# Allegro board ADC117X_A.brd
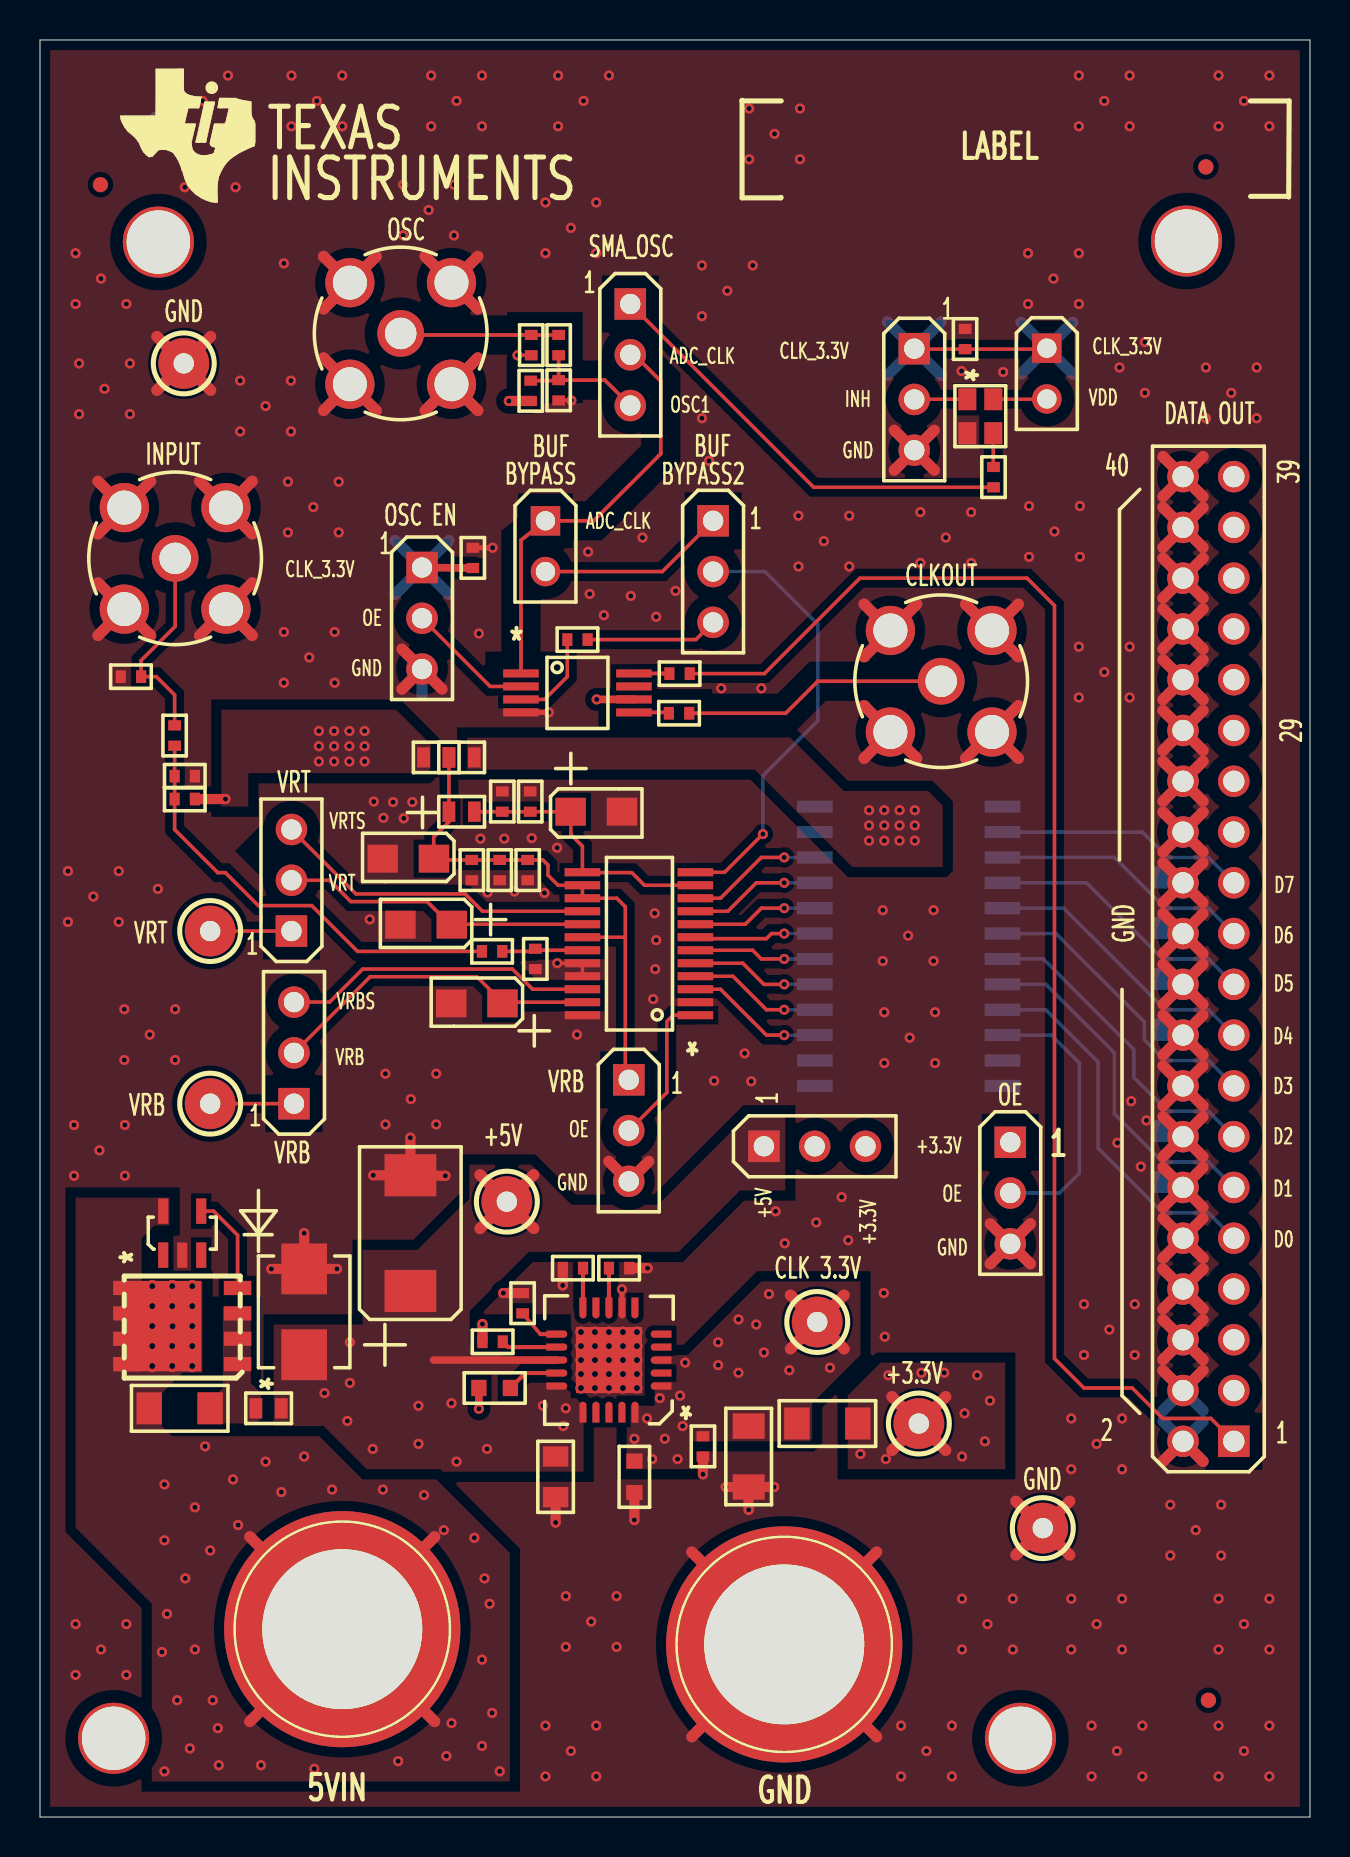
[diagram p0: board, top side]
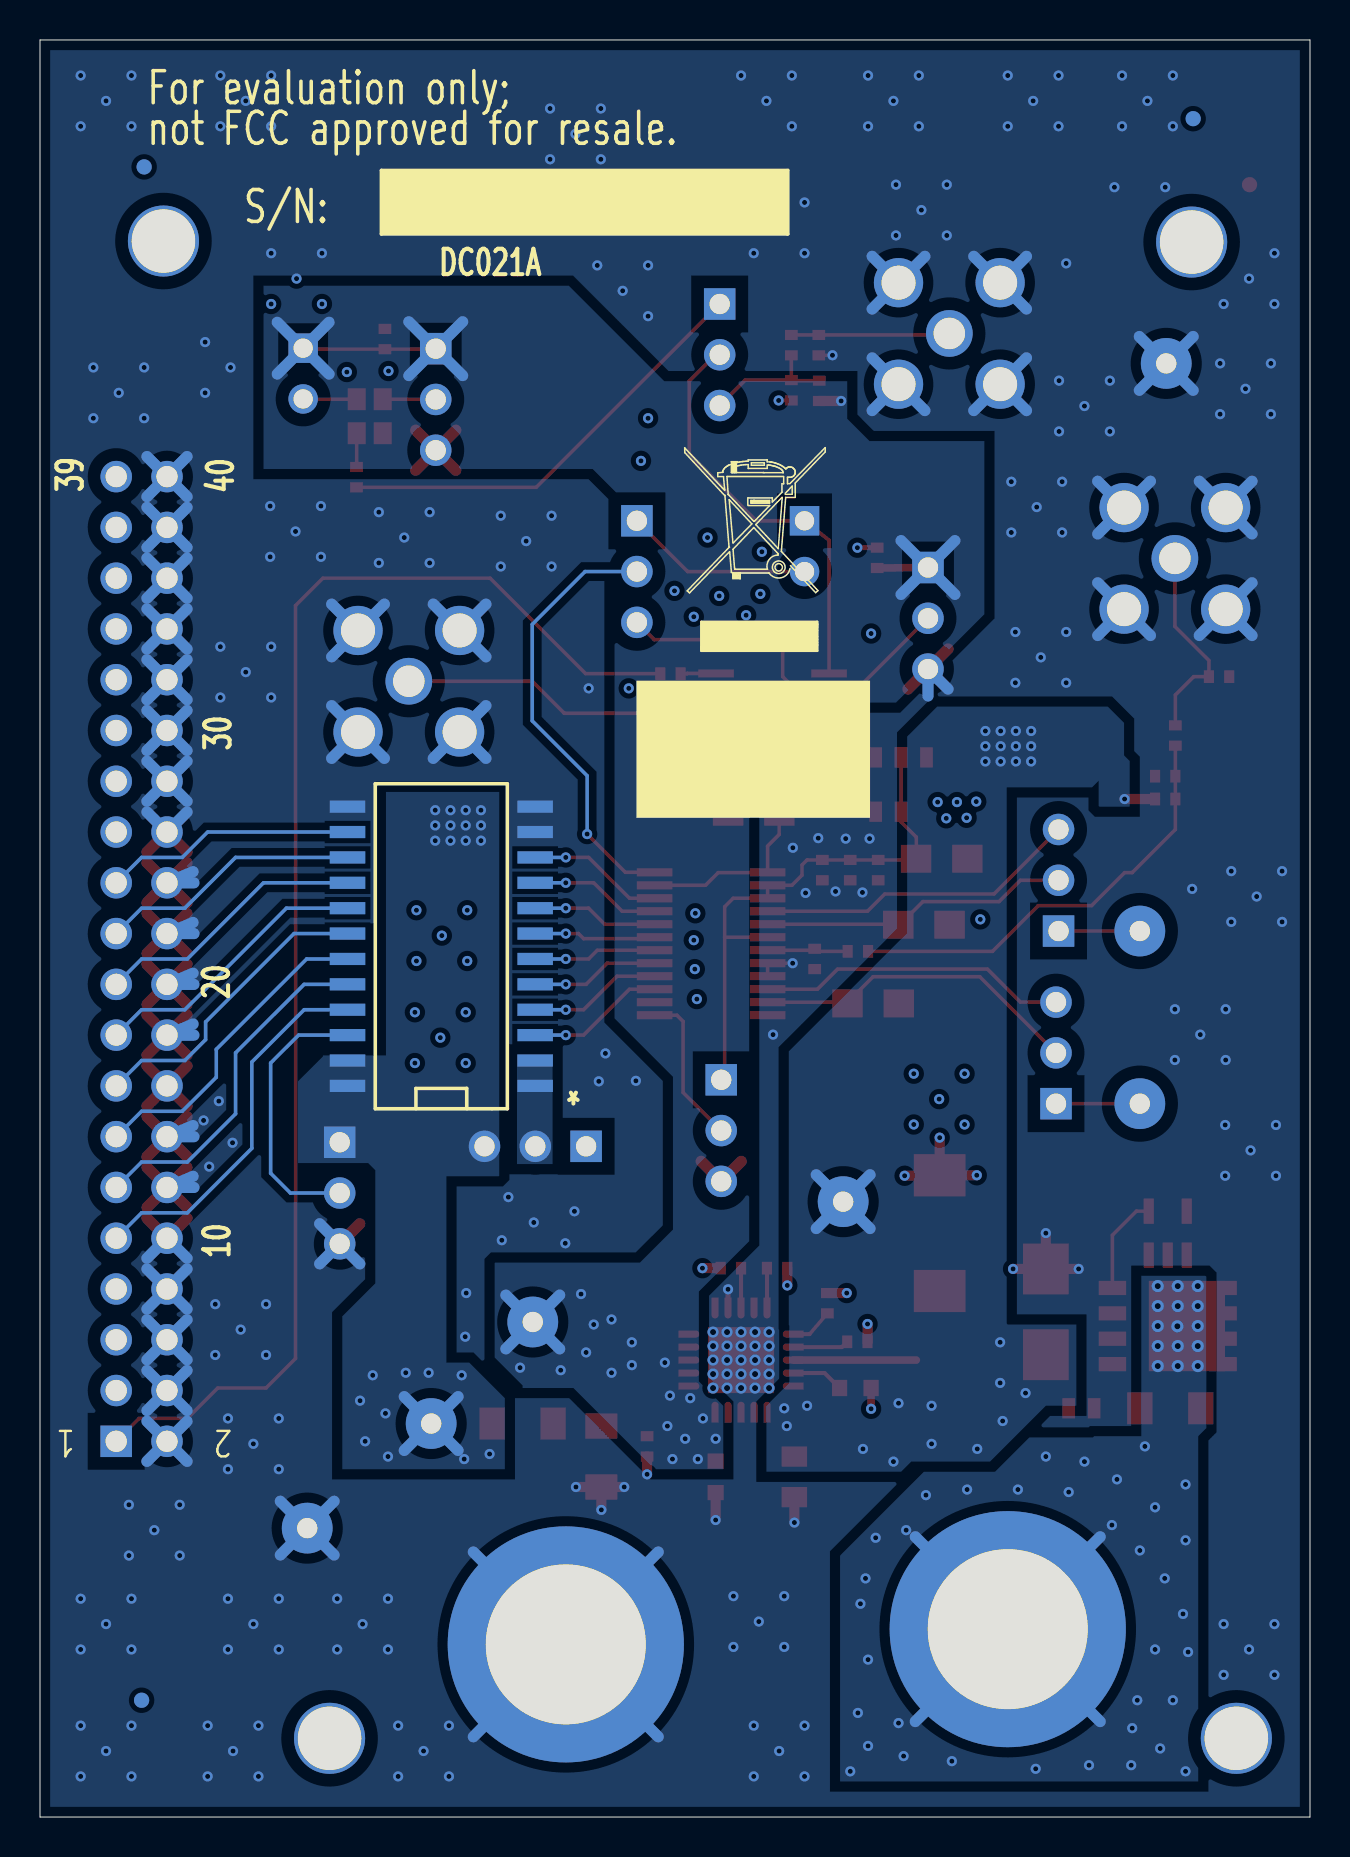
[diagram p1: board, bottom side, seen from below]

Outline 63.5 x 88.9 mm; copper layers: TOP, GND1, GND2, BOTTOM. Coordinates in mm from the lower left corner of the outline.
Outline path: 0,88.9 0,0 63.5,0 63.5,88.9 0,88.9

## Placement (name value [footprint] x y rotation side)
C1  10uF  [TANT_A]  18.41 47.94 180 top
C2  .1uF  [0402]  22.99 47.37 270 top
C3  .1uF  [0402]  21.59 47.37 270 top
C4  10uF  [TANT_A]  27.81 50.29 0 top
C5  .1uF  [0402]  24.51 50.8 90 top
C6  .1uF  [0402]  21.64 62.99 90 top
C7  10uF  [TANT_A]  19.3 44.64 180 top
C8  .01uF  [0402]  46.25 73.94 90 top
C9  .1uF  [0402]  25.93 73.63 270 top
C10  100uF  [TANT_D]  18.52 29.21 90 top
C11  10uF  [0805]  25.78 17.02 270 top
C12  .1uF  [0402]  33.15 18.54 270 top
C13  1.0uF  [0603]  29.72 17.02 270 top
C14  47uF  [1206]  35.43 18.03 270 top
C15  10uF  [TANT_A]  21.84 40.7 180 top
C16  .1uF  [0402]  24.38 47.37 270 top
C17  .1uF  [0402]  23.11 50.8 90 top
C20  1.0uF  [0603]  22.73 21.46 180 top
C21  1uF  [0402]  6.73 54.1 270 top
C22  15pF  [0402]  24.77 42.93 270 top
D1  S1AB-13-F  [DIODE_S1AB_SMB]  13.21 25.27 90 top
F1  FUSE 10A 63V FAST  [1206]  6.98 20.45 0 top
FB1  600 OHM @ 100MHz  [IND_0603]  21.08 50.29 180 top
FB2  330 OHM @ 100MHz  [IND_0603]  11.43 20.45 0 top
FB3  120 OHM @ 100MHz  [1206]  39.37 19.68 0 top
FB4  330 OHM @ 100MHz  [IND_0603]  19.81 53.01 0 top
FB5  330 OHM @ 100MHz  [IND_0603]  21.08 53.01 0 top
J1  HDR, THVT, 40POS, .100  [HDR_THVT_2X20_100_M]  59.69 18.8 180 top
J2  SMA, THVT,  50OHMS  [SMA_THVT_312X312]  45.06 56.82 0 top
J3  SMA, THVT,  50OHMS  [SMA_THVT_312X312]  18.03 74.22 0 top
J4  RED  [JACK_THVT_BANANA_315DRILL]  15.11 9.4 90 top
J5  BLK  [JACK_THVT_BANANA_315DRILL]  37.21 8.64 90 top
J6  SMA, THVT,  50OHMS  [SMA_THVT_312X312]  6.76 62.97 180 top
JP1  HEADER, 3POS, .100  [HDR_THVT_1X3_100_M]  43.71 73.46 0 top
JP2  HEADER, 3POS, .100  [HDR_THVT_1X3_100_M]  29.51 75.69 0 top
JP3  JUMPER_1X2_100  [HDR_THVT_1X2_100_M]  25.27 64.85 0 top
JP4  HEADER, 3POS, .100  [HDR_THVT_1X3_100_M]  19.1 62.51 0 top
JP5  HEADER, 3POS, .100  [HDR_THVT_1X3_100_M]  33.66 64.85 0 top
JP6  HEADER, 3POS, .100  [HDR_THVT_1X3_100_M]  12.7 35.69 180 top
JP7  HDR, 2POS, .100  [HDR_THVT_1X2_100_M]  50.34 73.48 0 top
JP8  HEADER, 3POS, .100  [HDR_THVT_1X3_100_M]  29.44 36.88 0 top
JP9  HEADER, 3POS, .100  [HDR_THVT_1X3_100_M]  12.57 44.32 180 top
JP10  JUMPER_1X3_100  [HDR_THVT_1X3_100_M]  48.51 33.76 0 top
JP11  HEADER, 3POS, .100  [HDR_THVT_1X3_100_M]  36.2 33.55 90 top
MT1  STANDOFF, FEMALE, 4-40 X  1/4"  [MFG125_PLATED]  5.92 78.79 0 top
MT2  STANDOFF, FEMALE, 4-40 X  1/4"  [MFG125_PLATED]  3.68 3.94 0 top
MT3  STANDOFF, FEMALE, 4-40 X  1/4"  [MFG125_PLATED]  49.02 3.94 0 top
MT4  STANDOFF, FEMALE, 4-40 X  1/4"  [MFG125_PLATED]  57.33 78.84 0 top
NOREF  -  [unnamed]  58.42 5.84 0 top
NOREF#2  -  [#2]  185.29 62.97 0 top
NOREF#3  -  [#2]  0 0 0 top
NOREF#4  -  [#2]  3.68 3.94 90 top
NOREF#5  -  [#2]  3.68 3.94 0 top
NOREF#6  -  [unnamed]  3.02 81.66 0 top
NOREF#7  -  [#2]  0 0 90 top
NOREF#8  -  [unnamed]  58.29 82.55 0 top
NOREF#9  -  [#2]  4.01 80.77 0 top
NOREF#10  -  [#2]  0 88.9 0 top
NOREF#11  -  [#2]  0 0 90 top
NOREF#12  -  [#2]  258.7 174.12 0 top
NOREF#13  -  [#2]  27.3 86.74 0 top
NOREF#14  -  [#2]  53.42 79.83 180 bottom
NOREF#15  -  [#2]  27.81 65.02 180 bottom
NOREF#16  -  [#2]  116.15 65.33 180 bottom
NOREF#17  -  [#2]  72.92 12.17 180 bottom
NOREF#18  -  [unnamed]  58.29 82.55 180 bottom
NOREF#19  -  [unnamed]  5.84 84.96 180 bottom
NOREF#20  -  [unnamed]  58.42 5.84 180 bottom
Q1  CSD18532Q5  [SON_Q5B_8]  7.11 24.56 180 top
R8  100  [0402]  24.54 71.35 90 top
R9  49.9  [0402]  24.56 73.63 90 top
R10  100  [0402]  25.93 71.37 270 top
R11  0  [0402]  22.63 23.77 0 top
R12  0  [0402]  24.13 25.7 270 top
R13  0  [0402]  26.64 27.46 0 top
R14  0  [0402]  28.96 27.46 180 top
R15  22.1  [0402]  26.87 58.9 180 top
R16  22.1  [0402]  31.95 55.22 0 top
R18  22.1  [0402]  31.98 57.2 0 top
R19  22.1  [0402]  47.68 67.03 90 top
R21  47  [0402]  22.61 43.31 180 top
R22  51  [0402]  4.55 57.05 180 top
R26  1.1k  [0402]  7.24 52.07 0 top
R30  4.22k  [0402]  7.24 50.93 0 top
TP1  BLK  [TP_THVT_100_RND_GND]  7.19 72.72 90 top
TP2  BLU  [TP_THVT_100_RND]  43.94 19.68 0 top
TP3  BLK  [TP_THVT_100_RND_GND]  50.14 14.45 0 top
TP4  BLU  [TP_THVT_100_RND]  38.86 24.77 0 top
TP5  BLU  [TP_THVT_100_RND]  8.51 44.32 0 top
TP6  BLU  [TP_THVT_100_RND]  8.51 35.69 0 top
TP7  BLU  [TP_THVT_100_RND]  23.34 30.78 0 top
U1  ADC1173  [TSSOP_24_311X177_26]  29.84 43.69 180 top
U2  TPS7A4700  [QFN20_RGW_P65PITCH]  28.45 22.86 180 top
U3  CDCV304PW  [TSSOP_8_177X122_26]  26.87 56.24 0 top
U4  TPS2400  [DBV5]  7.11 29.21 90 top
U5  74LVC8T245  [SOIC_24_610X299_50]  43.43 43.56 0 bottom
Y1  15MHz  [XTAL_4_SM_85X104]  47.02 70.08 270 top

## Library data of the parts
C1 C4 C7 C15 = CAP_TANT_A_0
C2 C3 C5 C6 C9 C16 C17 C21 C22 = CAP_0402_0.1uF
C8 = CAP_0402_0.01uF
C10 = CAP_TANT_D_0
C11 = CAP NP_1: tolerance: 10%
C12 = CAP0603: tolerance: 10%
C13 C20 = CAP NP_0: tolerance: 10%
C14 = CAP NP_0: tolerance: 20%
D1 = DIODE_S1BB
F1 = FUSE_0
FB1 FB2 FB4 FB5 = FERRITE_BEAD_0603_600_H
FB3 = FERRITE_BEAD_1206_120_H
J1 = HEADER_2x20_100
J2 J3 J6 = TMP_102603
J4 = BANANA_JACK_RED_RoHS
J5 = BANANA_JACK_BLK_RoHS
JP1 JP2 JP4 JP5 JP8 JP10 JP11 = JUMPER_1X3_100
JP3 JP7 = JUMPER_1X2_100
JP6 JP9 = HEADER_1x3_100
MT1-MT4 = MOUNTING_HOLE_1_3/16"
Q1 = CSD18532Q5B
R8 R10 = Res_0402_100
R9 = Res_0402_49.9_H
R11-R14 = R: tolerance: 5%
R15 R16 R18 R19 = Res_0402_22.1_H
R21 = Res_0402_47
R22 = Res_0402_51_.5%: tolerance: .1%
R26 = Res_0805_21.5k
R30 = Res_0402_1.2k
TP1 TP3 = TESTPOINT_BLK
TP2 TP4-TP7 = TESTPOINT_BLUE
U1 = ADC1175
U2 = TPS7A4700
U3 = CDCV304PW
U4 = TPS2400
U5 = SN74LVC8T245
Y1 = OSC_4_SM_KYOCERA_40MHz

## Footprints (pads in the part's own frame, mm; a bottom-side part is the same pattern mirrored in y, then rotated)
0402
  rect 0.508x0.635 smd: 1(-0.508,0) 2(0.508,0)
0603
  rect 0.762x0.813 smd: 1(-0.787,0) 2(0.787,0)
0805
  rect 1.016x1.27 smd: 1(-1.016,0) 2(1.016,0)
1206
  rect 1.27x1.6 smd: 1(-1.524,0) 2(1.524,0)
DBV5
  rect 1.27x0.508 smd: 1(-1.1,0.95) 2(-1.1,0) 3(-1.1,-0.95) 4(1.1,-0.95) 5(1.1,0.95)
DIODE_S1AB_SMB
  rect 2.54x2.286 smd: 1(2.146,0) 2(-2.146,0)
HDR_THVT_1X2_100_M
  rect 1.473x1.473 hole 0.965: 1(0,0)
  round 1.473 hole 0.965: 2(0,-2.54)
HDR_THVT_1X3_100_M
  rect 1.575x1.575 hole 1.016: 1(0,0)
  round 1.575 hole 1.016: 2(0,-2.54) 3(0,-5.08)
HDR_THVT_2X20_100_M
  rect 1.575x1.575 hole 1.067: 1(0,0)
  round 1.575 hole 1.067: 2(2.54,0) 3(0,-2.54) 4(2.54,-2.54) 5(0,-5.08) 6(2.54,-5.08) 7(0,-7.62) 8(2.54,-7.62) 9(0,-10.16) 10(2.54,-10.16) 11(0,-12.7) 12(2.54,-12.7) 13(0,-15.24) 14(2.54,-15.24) 15(0,-17.78) 16(2.54,-17.78) 17(0,-20.32) 18(2.54,-20.32) 19(0,-22.86) 20(2.54,-22.86) 21(0,-25.4) 22(2.54,-25.4) 23(0,-27.94) 24(2.54,-27.94) 25(0,-30.48) 26(2.54,-30.48) 27(0,-33.02) 28(2.54,-33.02) 29(0,-35.56) 30(2.54,-35.56) 31(0,-38.1) 32(2.54,-38.1) 33(0,-40.64) 34(2.54,-40.64) 35(0,-43.18) 36(2.54,-43.18) 37(0,-45.72) 38(2.54,-45.72) 39(0,-48.26) 40(2.54,-48.26)
IND_0603
  rect 0.635x1.016 smd: 1(-0.635,0) 2(0.635,0)
JACK_THVT_BANANA_315DRILL
  round 11.811 hole 8.001: 1(0,0)
MFG125_PLATED
  round 3.556 hole 3.175: 1(0,0)
QFN20_RGW_P65PITCH
  custom 0.09x0.09 smd: 1(-2.607,1.3) 2(-2.607,0.65) 3(-2.607,0) 4(-2.607,-0.65) 5(-2.607,-1.3) 6(-1.3,-2.607) 7(-0.65,-2.607) 8(0,-2.607) 9(0.65,-2.607) 10(1.3,-2.607) 11(2.607,-1.3) 12(2.607,-0.65) 13(2.607,0) 14(2.607,0.65) 15(2.607,1.3) 16(1.3,2.607) 17(0.65,2.607) 18(0,2.607) 19(-0.65,2.607) 20(-1.3,2.607)
  rect 3.302x3.302 smd: 21(0,0)
SMA_THVT_312X312
  round 2.337 hole 1.575: 1(0,0)
  round 2.464 hole 1.702: 2(-2.54,2.54) 3(2.54,2.54) 4(2.54,-2.54) 5(-2.54,-2.54)
SOIC_24_610X299_50
  rect 1.778x0.61 smd: 1(-4.69,6.985) 2(-4.69,5.715) 3(-4.69,4.445) 4(-4.69,3.175) 5(-4.69,1.905) 6(-4.69,0.635) 7(-4.69,-0.635) 8(-4.69,-1.905) 9(-4.69,-3.175) 10(-4.69,-4.445) 11(-4.69,-5.715) 12(-4.69,-6.985) 13(4.69,-6.985) 14(4.69,-5.715) 15(4.69,-4.445) 16(4.69,-3.175) 17(4.69,-1.905) 18(4.69,-0.635) 19(4.69,0.635) 20(4.69,1.905) 21(4.69,3.175) 22(4.69,4.445) 23(4.69,5.715) 24(4.69,6.985)
SON_Q5B_8
  rect 1.372x0.711 smd: 1(-2.767,1.905) 2(-2.767,0.635) 3(-2.767,-0.635) 4(-2.767,-1.905) 5(2.767,-1.905) 6(2.767,-0.635) 7(2.767,0.635) 8(2.767,1.905)
TANT_A
  rect 1.524x1.397 smd: 1(-1.283,0) 2(1.283,0)
TANT_D
  rect 2.108x2.591 smd: 1(-2.896,0) 2(2.896,0)
TP_THVT_100_RND
  round 2.54 hole 1.016: 1(0,0)
TP_THVT_100_RND_GND
  round 2.54 hole 1.016: 1(0,0)
TSSOP_8_177X122_26
  rect 1.778x0.406 smd: 1(-2.825,0.975) 2(-2.825,0.325) 3(-2.825,-0.325) 4(-2.825,-0.975) 5(2.825,-0.975) 6(2.825,-0.325) 7(2.825,0.325) 8(2.825,0.975)
TSSOP_24_311X177_26
  rect 1.778x0.406 smd: 1(-2.925,3.575) 2(-2.925,2.925) 3(-2.925,2.275) 4(-2.925,1.625) 5(-2.925,0.975) 6(-2.925,0.325) 7(-2.925,-0.325) 8(-2.925,-0.975) 9(-2.925,-1.625) 10(-2.925,-2.275) 11(-2.925,-2.925) 12(-2.925,-3.575) 13(2.725,-3.575) 14(2.725,-2.925) 15(2.725,-2.275) 16(2.725,-1.625) 17(2.725,-0.975) 18(2.725,-0.325) 19(2.725,0.325) 20(2.725,0.975) 21(2.725,1.625) 22(2.725,2.275) 23(2.725,2.925) 24(2.725,3.575)
unnamed
  round 0.762 smd: (0,0)
XTAL_4_SM_85X104
  rect 1.1x0.9 smd: 1(-0.85,-0.65) 2(0.85,-0.65) 3(0.85,0.65) 4(-0.85,0.65)

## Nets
5V: F1.1 J4.1 Q1.5(D5) Q1.6(D6) Q1.7(D7) Q1.8(D8) U4.5(VIN)
+3.3V: FB3.2 FB5.2 JP10.1(PIN1) JP11.3(PIN3) TP2.1(TP) U5.23(VCCB2) U5.24(VCCB1)
+5V: C10.1 C11.1 D1.2(CATHODE) FB2.2 FB4.1 JP11.1(PIN1) R30.2 TP7.1(TP) U2.13(EN) U2.15(IN2) U2.16(IN1)
GND: C1.2 C2.2 C3.2 C4.2 C5.2 C6.2 C7.2 C8.2 C10.2 C11.2 C12.2 C13.2 C14.2 C15.2 C16.2 C17.2 C20.2 C22.2 D1.1(ANODE) J1.2 J1.4 J1.6 J1.8 J1.10 J1.12 J1.14 J1.16 J1.18 J1.20 J1.22 J1.24 J1.26 J1.28 J1.30 J1.32 J1.34 J1.36 J1.38 J1.40 J2.2(GND#2) J2.3(GND#3) J2.4(GND#4) J2.5(GND#5) J3.2(GND#2) J3.3(GND#3) J3.4(GND#4) J3.5(GND#5) J5.1 J6.2(GND#2) J6.3(GND#3) J6.4(GND#4) J6.5(GND#5) JP1.3(PIN3) JP4.3(PIN3) JP8.3(PIN3) JP10.3(PIN3) R9.1 R10.2 R11.1 R12.1 R13.1 R14.1 R22.2 R26.2 TP1.1(TP) TP3.1(TP) U1.2(DVSS#2) U1.20(AVSS#20) U1.21(AVSS#21) U1.24(DVSS#24) U2.7(GND) U2.21(PWRPAD) U3.4(GND) U4.2(GND) U5.11(GND1) U5.12(GND2) U5.13(GND3) Y1.2(GND)
ADC_CLK: JP2.2(PIN2) JP3.1 U3.1(CLKIN)
CLK_3.3V: C6.1 C8.1 C12.1 C13.1 C14.1 FB3.1 JP1.1(PIN1) JP4.1(PIN1) JP7.1 R8.1 TP4.1(TP) U2.1(OUT1) U2.3(SENSE) U2.20(OUT2) U3.6(VDD3.3V)
CLK_OUT: J2.1(CENTER) R16.2
CLKOUT: R16.1 U3.5(X1Y1)
D0: U1.3(D0) U5.3(A1)
D1: U1.4(D1) U5.4(A2)
D2: U1.5(D2) U5.5(A3)
D3: U1.6(D3) U5.6(A4)
D4: U1.7(D4) U5.7(A5)
D5: U1.8(D5) U5.8(A6)
D6: U1.9(D6) U5.9(A7)
D7: U1.10(D7) U5.10(A8)
OE: JP4.2(PIN2) U3.2(OE)
OSC: C9.1 J3.1(CENTER) R9.2
OSC1: C9.2 JP2.3(PIN3) R8.2 R10.1
X1Y3: J1.1 R18.2
N19769118: R19.2 Y1.3(OUT)
N19769226: JP2.1(PIN1) R19.1
N19799665: R15.2 U3.3(X1Y0)
N19799687: R18.1 U3.8(X1Y3)
N19818955: J1.23 U5.14(B8)
N19818957: J1.21 U5.15(B7)
N19818959: J1.19 U5.16(B6)
N19818961: J1.17 U5.17(B5)
N19819026: J1.9 U5.21(B1)
N19819028: J1.11 U5.20(B2)
N19819030: J1.13 U5.19(B3)
N19819032: J1.15 U5.18(B4)
N19819185: JP3.2 JP5.1(PIN1)
N19819194: JP5.2(PIN2) U1.12(CLK)
N19819218: JP5.3(PIN3) R15.1
N19821064: JP1.2(PIN2) Y1.1(INH)
N19821339: JP7.2 Y1.4(VDD)
N19861116: C1.1 C2.1 C3.1 C16.1 FB1.2 FB4.2 FB5.1 JP8.1(PIN1) U1.14(AVDD#14) U1.15(AVDD#15) U1.18(AVDD#18)
N19861142: C4.1 C5.1 C17.1 FB1.1 U1.11(DVDD#11) U1.13(DVDD#13)
N19864072: C21.1 J6.1(CENTER) R22.1
N19864307: C22.1 R21.1 U1.19(VIN)
N19864545: JP8.2(PIN2) U1.1(\\O\E\)
N19865533: JP9.3 U1.16(VRTS)
N19865546: C7.1 JP9.2 U1.17(VRT)
N19865555: JP9.1 TP5.1(TP)
N19865562: C15.1 JP6.2 U1.23(VRB)
N19865571: JP6.3 U1.22(VRBS)
N19865580: JP6.1 TP6.1(TP)
N19873407: C20.1 U2.14(NR)
N19873435: R14.2 U2.8(1P6V)
N19873437: R12.2 U2.11(0P2V)
N19873439: R11.2 U2.12(0P1V)
N19873449: R13.2 U2.10(0P4V)
N19874252: F1.2 FB2.1 Q1.1(S1) Q1.2(S2) Q1.3(S3)
N19874302: Q1.4(G) U4.4(GATE)
N19886844: JP10.2(PIN2) U5.22(O\E\)
N19887644: JP11.2(PIN2) U5.1(VCCA) U5.2(DIR)
N19913177: C21.2 R21.2 R26.1 R30.1

Pads without a net: J1 3 5 7 25 27 29 31 33 35 37 39; MT1 1; MT2 1; MT3 1; MT4 1; U2 2 4 5 6 9 17 18 19; U3 7; U4 1 3

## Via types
v1: diameter 0.508, hole 0.254, TOP to BOTTOM, 381 vias
v2: diameter 0.61, hole 0.305, TOP to BOTTOM, 15 vias
v3: diameter 0.559, hole 0.305, TOP to BOTTOM, 25 vias

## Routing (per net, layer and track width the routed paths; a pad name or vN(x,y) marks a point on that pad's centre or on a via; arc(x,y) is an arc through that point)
5V: length 52.3
  TOP w0.559: 10.49,4.78 J4.1 ; J4.1 19.74,4.78 ; J4.1 19.74,14.02 ; J4.1 10.49,14.02
  BOTTOM w0.559: J4.1 19.74,4.78 ; J4.1 10.49,14.02 ; J4.1 10.49,4.78 ; J4.1 19.74,14.02
  vias: v1(6.1,8.25) v1(6.22,16.64) v1(6.22,13.84) v1(6.22,2.29) v1(6.35,10.16) v1(6.86,5.84) v1(7.26,11.94) v1(7.49,3.43) v1(7.75,15.49) v1(7.75,8.38) v1(8.25,18.54) v1(8.51,13.33) v1(8.64,5.84) v1(8.89,4.45) v1(8.94,2.59) v1(9.65,16.89) v1(9.91,14.6) v1(11.05,2.59) v1(11.28,17.78) v1(12.06,16.26) v1(13.21,18.03) v1(13.72,2.41) v1(14.61,16.38) v1(17.14,16.38) v1(17.91,2.79) v1(19.2,16.1) v1(20.19,14.35) v1(20.32,3.05) v1(20.57,4.7) v1(21.72,13.97) v1(22.1,7.87) v1(22.1,3.56) v1(22.23,11.94) v1(22.48,10.67) v1(22.61,5.21) v1(22.99,2.29) v2(5.61,26.56) v2(5.61,25.56) v2(5.61,24.56) v2(5.61,23.56) v2(5.61,22.56) v2(6.61,26.56) v2(6.61,25.56) v2(6.63,24.55) v2(6.61,23.56) v2(6.61,22.56) v2(7.61,26.56) v2(7.61,25.56) v2(7.61,24.56) v2(7.61,23.56) v2(7.61,22.56)
+3.3V: length 15.2
  TOP w0.559: TP2.1 45.29,18.34 ; TP2.1 45.29,21.03 ; TP2.1 42.6,18.34 ; TP2.1 42.6,21.03
  BOTTOM w0.559: TP2.1 45.29,21.03 ; TP2.1 42.6,18.34 ; TP2.1 45.29,18.34 ; TP2.1 42.6,21.03
  vias: v1(41.02,18.16) v1(41.45,50.37) v1(41.45,49.61) v1(41.45,48.84) v1(42.21,50.37) v1(42.21,49.61) v1(42.21,48.84) v1(42.29,17.91) v1(42.42,22.1) v1(42.98,50.37) v1(42.98,49.61) v1(42.98,48.84) v1(43.74,50.37) v1(43.74,49.61) v1(43.74,48.84) v1(44.07,22.23) v1(45.21,22.23) v1(46.1,18.03) v1(46.23,20.19) v1(46.86,22.1) v1(47.24,18.8) v1(47.5,20.83)
+5V: length 22.9
  TOP w0.381: U2.13 19.68,22.86
  TOP w0.508: R30.2 v1(9.27,50.93)
  TOP w0.559: 22,29.44 TP7.1 ; TP7.1 22,32.13 ; TP7.1 24.69,29.44 ; TP7.1 24.69,32.13
  BOTTOM w0.559: 22,29.44 TP7.1 ; TP7.1 24.69,29.44 ; TP7.1 22,32.13 ; TP7.1 24.69,32.13
  vias: v1(13.94,54.33) v1(13.94,53.57) v1(13.94,52.81) v1(14.22,21.21) v1(14.71,54.33) v1(14.71,53.57) v1(14.71,52.81) v1(15.37,19.81) v1(15.47,54.33) v1(15.47,53.57) v1(15.47,52.81) v1(15.49,23.75) v1(15.49,21.72) v1(16.23,54.33) v1(16.23,53.57) v1(16.23,52.81) v1(16.64,18.41) v1(18.92,20.57) v1(18.92,18.67) v1(20.57,20.7) v1(20.83,17.78) v1(22.35,18.41) v1(25.15,20.57) v1(26.16,19.56) v1(26.29,20.45)
GND: length 952.9
  TOP w0.178: U1.21 U1.20 v1(25.87,42.71) ; R9.1 v1(23.88,73.13) ; R10.2 v1(26.57,70.87)
  TOP w0.254: U3.4 v1(25.44,55.26) ; U2.7 v1(29.1,26.4) ; C6.2 v1(22.63,63.5)
  TOP w0.381: C20.2 v1(21.95,20.42)
  TOP w0.508: R11.1 v1(22.12,24.66) ; C14.2 v1(36.7,16.51) ; C14.2 v1(35.43,15.37) ; C14.2 v1(34.29,16.51) ; C11.2 v1(25.78,14.73) ; D1.1 v1(14.85,27.42) ; D1.1 v1(11.57,27.42) ; D1.1 v1(13.21,29.21) ; R12.1 v1(23.16,26.21) ; C13.2 v1(29.72,14.86) ; R13.1 v1(26.14,26.59) ; 33.15,18.03 v1(33.15,17.14) ; C10.2 v1(20.27,32.08) ; C10.2 v1(18.52,33.99) ; C10.2 v1(16.66,32.11) ; R14.1 v1(30.38,27.46)
  TOP w0.559: J1.40 58.15,68.06 ; J1.40 58.15,66.05 ; J1.40 56.15,66.05 ; J1.40 56.15,68.06 ; 5.84,71.38 TP1.1 ; TP1.1 8.53,74.06 ; TP1.1 8.53,71.38 ; TP1.1 5.84,74.06 ; 56.15,55.36 J1.30 ; J1.30 58.15,55.36 ; J1.30 58.15,53.35 ; J1.30 56.15,53.35 ; J6.2 10.61,59.11 ; J6.2 10.61,61.74 ; J6.2 7.98,59.11 ; J1.24 58.15,47.74 ; J1.24 56.15,45.73 ; J1.24 56.15,47.74 ; J1.24 58.15,45.73 ; 56.15,40.65 J1.20 ; J1.20 58.15,40.65 ; J1.20 56.15,42.66 ; J1.20 58.15,42.66 ; 2.9,66.82 J6.4 ; J6.4 5.53,66.82 ; J6.4 2.9,64.19 ; 2.9,59.11 J6.3 ; J6.3 2.9,61.74 ; J6.3 5.53,59.11 ; J1.16 58.15,35.57 ; J1.16 56.15,35.57 ; J1.16 56.15,37.58 ; J1.16 58.15,37.58 ; 56.15,62.98 J1.36 ; J1.36 58.15,60.97 ; J1.36 58.15,62.98 ; J1.36 56.15,60.97 ; 56.15,32.5 57.15,31.5 ; 57.15,31.5 56.15,30.49 ; 57.15,31.5 58.15,30.49 ; 57.15,31.5 58.15,32.5 ; 56.15,38.11 J1.18 ; J1.18 58.15,38.11 ; J1.18 56.15,40.12 ; J1.18 58.15,40.12 ; J1.6 58.15,24.88 ; J1.6 56.15,22.87 ; J1.6 58.15,22.87 ; J1.6 56.15,24.88 ; JP1.3 44.72,67.37 ; JP1.3 44.72,69.38 ; JP1.3 42.71,67.37 ; JP1.3 42.71,69.38 ; 56.15,17.79 J1.2 58.15,17.79 ; J5.1 41.83,13.26 ; J5.1 32.59,13.26 ; J5.1 32.59,4.01 ; J5.1 41.83,4.01 ; J3.5 16.81,70.36 ; J3.5 14.18,73 ; J3.5 14.18,70.36 ; 41.2,58.04 J2.2 ; J2.2 41.2,60.68 ; J2.2 43.84,60.68 ; 56.15,50.28 J1.26 ; J1.26 56.15,48.27 ; J1.26 58.15,50.28 ; J1.26 58.15,48.27 ; JP10.3 49.52,29.68 ; JP10.3 47.51,27.67 ; JP10.3 49.52,27.67 ; JP10.3 47.51,29.68 ; J3.3 21.89,78.08 ; J3.3 21.89,75.44 ; J3.3 19.26,78.08 ; J2.4 48.92,55.6 ; J2.4 48.92,52.96 ; J2.4 46.28,52.96 ; J1.34 58.15,58.43 ; J1.34 58.15,60.44 ; J1.34 56.15,60.44 ; J1.34 56.15,58.43 ; 56.15,43.19 J1.22 ; J1.22 58.15,43.19 ; J1.22 58.15,45.2 ; J1.22 56.15,45.2 ; 56.15,29.96 J1.10 ; J1.10 58.15,27.95 ; J1.10 56.15,27.95 ; J1.10 58.15,29.96 ; 7.98,66.82 J6.5 ; J6.5 10.61,64.19 ; J6.5 10.61,66.82 ; 46.28,60.68 J2.3 ; J2.3 48.92,60.68 ; J2.3 48.92,58.04 ; 56.15,35.04 J1.14 ; J1.14 58.15,35.04 ; J1.14 56.15,33.03 ; J1.14 58.15,33.03 ; 14.18,75.44 J3.2 ; J3.2 16.81,78.08 ; J3.2 14.18,78.08 ; 56.15,55.89 J1.32 ; J1.32 58.15,55.89 ; J1.32 58.15,57.9 ; J1.32 56.15,57.9 ; 56.15,25.41 J1.8 ; J1.8 56.15,27.42 ; J1.8 58.15,25.41 ; J1.8 58.15,27.42 ; 18.1,58.43 JP4.3 ; JP4.3 20.1,56.43 ; JP4.3 18.1,56.43 ; 56.15,52.82 J1.28 ; J1.28 58.15,50.81 ; J1.28 58.15,52.82 ; J1.28 56.15,50.81 ; 41.2,55.6 J2.5 ; J2.5 41.2,52.96 ; J2.5 43.84,52.96 ; 56.15,65.52 J1.38 ; J1.38 58.15,63.51 ; J1.38 58.15,65.52 ; J1.38 56.15,63.51 ; J3.4 21.89,73 ; J3.4 19.26,70.36 ; J3.4 21.89,70.36 ; TP3.1 51.48,13.11 ; TP3.1 48.8,13.11 ; TP3.1 48.8,15.8 ; TP3.1 51.48,15.8 ; 58.15,22.34 J1.4 56.15,22.34 ; 30.44,32.8 JP8.3 28.44,32.8
  GND1 w0.559: 48.8,15.8 TP3.1 ; TP3.1 51.48,15.8 ; TP3.1 51.48,13.11 ; TP3.1 48.8,13.11 ; J1.24 58.15,47.74 ; J1.24 56.15,47.74 ; J1.24 58.15,45.73 ; J1.24 56.15,45.73 ; 56.15,37.58 J1.16 ; J1.16 58.15,37.58 ; J1.16 58.15,35.57 ; J1.16 56.15,35.57 ; J2.5 43.84,52.96 ; J2.5 41.2,55.6 ; J2.5 41.2,52.96 ; J6.3 5.53,59.11 ; J6.3 2.9,59.11 ; J6.3 2.9,61.74 ; 14.18,73 J3.5 ; J3.5 14.18,70.36 ; J3.5 16.81,70.36 ; 41.2,60.68 J2.2 ; J2.2 43.84,60.68 ; J2.2 41.2,58.04 ; J1.2 58.15,19.8 ; J1.2 58.15,17.79 ; J1.2 56.15,17.79 ; J1.2 56.15,19.8 ; J3.4 21.89,70.36 ; J3.4 21.89,73 ; J3.4 19.26,70.36 ; JP4.3 20.1,56.43 ; JP4.3 18.1,56.43 ; JP4.3 18.1,58.43 ; JP4.3 20.1,58.43 ; J1.8 58.15,27.42 ; J1.8 56.15,25.41 ; J1.8 58.15,25.41 ; J1.8 56.15,27.42 ; JP8.3 30.44,30.8 ; JP8.3 28.44,32.8 ; JP8.3 28.44,30.8 ; JP8.3 30.44,32.8 ; 56.15,27.95 J1.10 ; J1.10 58.15,29.96 ; J1.10 56.15,29.96 ; J1.10 58.15,27.95 ; J1.26 58.15,48.27 ; J1.26 56.15,50.28 ; J1.26 58.15,50.28 ; J1.26 56.15,48.27 ; 56.15,30.49 57.15,31.5 ; 57.15,31.5 56.15,32.5 ; 57.15,31.5 58.15,32.5 ; 57.15,31.5 58.15,30.49 ; 56.15,24.88 J1.6 ; J1.6 58.15,22.87 ; J1.6 56.15,22.87 ; J1.6 58.15,24.88 ; 56.15,50.81 J1.28 ; J1.28 58.15,52.82 ; J1.28 56.15,52.82 ; J1.28 58.15,50.81 ; 42.71,67.37 JP1.3 ; JP1.3 42.71,69.38 ; JP1.3 44.72,69.38 ; JP1.3 44.72,67.37 ; 56.15,40.12 J1.18 ; J1.18 58.15,40.12 ; J1.18 56.15,38.11 ; J1.18 58.15,38.11 ; 56.15,43.19 J1.22 ; J1.22 58.15,45.2 ; J1.22 56.15,45.2 ; J1.22 58.15,43.19 ; J1.30 58.15,53.35 ; J1.30 56.15,53.35 ; J1.30 58.15,55.36 ; J1.30 56.15,55.36 ; J1.32 58.15,57.9 ; J1.32 58.15,55.89 ; J1.32 56.15,55.89 ; J1.32 56.15,57.9 ; J2.4 48.92,55.6 ; J2.4 48.92,52.96 ; J2.4 46.28,52.96 ; 5.84,74.06 TP1.1 ; TP1.1 8.53,71.38 ; TP1.1 5.84,71.38 ; TP1.1 8.53,74.06 ; J3.2 16.81,78.08 ; J3.2 14.18,78.08 ; J3.2 14.18,75.44 ; J5.1 41.83,4.01 ; J5.1 32.59,4.01 ; J5.1 41.83,13.26 ; J5.1 32.59,13.26 ; 56.15,22.34 J1.4 ; J1.4 58.15,20.33 ; J1.4 58.15,22.34 ; J1.4 56.15,20.33 ; 56.15,58.43 J1.34 ; J1.34 58.15,58.43 ; J1.34 58.15,60.44 ; J1.34 56.15,60.44 ; 56.15,63.51 J1.38 ; J1.38 58.15,65.52 ; J1.38 56.15,65.52 ; J1.38 58.15,63.51 ; 56.15,66.05 J1.40 ; J1.40 56.15,68.06 ; J1.40 58.15,68.06 ; J1.40 58.15,66.05 ; J6.5 10.61,64.19 ; J6.5 7.98,66.82 ; J6.5 10.61,66.82 ; J3.3 21.89,75.44 ; J3.3 21.89,78.08 ; J3.3 19.26,78.08 ; J1.36 58.15,60.97 ; J1.36 58.15,62.98 ; J1.36 56.15,60.97 ; J1.36 56.15,62.98 ; JP10.3 49.52,27.67 ; JP10.3 47.51,29.68 ; JP10.3 49.52,29.68 ; JP10.3 47.51,27.67 ; 2.9,64.19 J6.4 ; J6.4 5.53,66.82 ; J6.4 2.9,66.82 ; J6.2 10.61,59.11 ; J6.2 10.61,61.74 ; J6.2 7.98,59.11 ; 56.15,35.04 J1.14 ; J1.14 56.15,33.03 ; J1.14 58.15,35.04 ; J1.14 58.15,33.03 ; J1.20 58.15,40.65 ; J1.20 56.15,40.65 ; J1.20 58.15,42.66 ; J1.20 56.15,42.66 ; J2.3 48.92,58.04 ; J2.3 46.28,60.68 ; J2.3 48.92,60.68
  GND2 w0.559: 56.15,25.41 J1.8 ; J1.8 58.15,27.42 ; J1.8 56.15,27.42 ; J1.8 58.15,25.41 ; 56.15,43.19 J1.22 ; J1.22 58.15,45.2 ; J1.22 56.15,45.2 ; J1.22 58.15,43.19 ; J1.34 58.15,60.44 ; J1.34 58.15,58.43 ; J1.34 56.15,60.44 ; J1.34 56.15,58.43 ; J1.10 58.15,29.96 ; J1.10 56.15,27.95 ; J1.10 58.15,27.95 ; J1.10 56.15,29.96 ; 56.15,24.88 J1.6 ; J1.6 58.15,22.87 ; J1.6 56.15,22.87 ; J1.6 58.15,24.88 ; 48.8,15.8 TP3.1 ; TP3.1 51.48,13.11 ; TP3.1 51.48,15.8 ; TP3.1 48.8,13.11 ; 14.18,78.08 J3.2 ; J3.2 16.81,78.08 ; J3.2 14.18,75.44 ; 56.15,32.5 57.15,31.5 ; 57.15,31.5 58.15,30.49 ; 57.15,31.5 56.15,30.49 ; 57.15,31.5 58.15,32.5 ; J1.26 58.15,48.27 ; J1.26 56.15,48.27 ; J1.26 58.15,50.28 ; J1.26 56.15,50.28 ; J1.36 58.15,60.97 ; J1.36 58.15,62.98 ; J1.36 56.15,60.97 ; J1.36 56.15,62.98 ; 41.2,55.6 J2.5 ; J2.5 43.84,52.96 ; J2.5 41.2,52.96 ; JP1.3 44.72,69.38 ; JP1.3 44.72,67.37 ; JP1.3 42.71,69.38 ; JP1.3 42.71,67.37 ; 56.15,40.65 J1.20 ; J1.20 56.15,42.66 ; J1.20 58.15,40.65 ; J1.20 58.15,42.66 ; 7.98,59.11 J6.2 ; J6.2 10.61,61.74 ; J6.2 10.61,59.11 ; 46.28,60.68 J2.3 ; J2.3 48.92,58.04 ; J2.3 48.92,60.68 ; TP1.1 8.53,74.06 ; TP1.1 8.53,71.38 ; TP1.1 5.84,71.38 ; TP1.1 5.84,74.06 ; 14.18,70.36 J3.5 ; J3.5 16.81,70.36 ; J3.5 14.18,73 ; 47.51,29.68 JP10.3 ; JP10.3 47.51,27.67 ; JP10.3 49.52,27.67 ; JP10.3 49.52,29.68 ; 41.2,58.04 J2.2 ; J2.2 43.84,60.68 ; J2.2 41.2,60.68 ; J1.14 58.15,35.04 ; J1.14 56.15,33.03 ; J1.14 58.15,33.03 ; J1.14 56.15,35.04 ; J1.30 58.15,55.36 ; J1.30 56.15,53.35 ; J1.30 58.15,53.35 ; J1.30 56.15,55.36 ; 2.9,64.19 J6.4 ; J6.4 2.9,66.82 ; J6.4 5.53,66.82 ; 7.98,66.82 J6.5 ; J6.5 10.61,66.82 ; J6.5 10.61,64.19 ; 56.15,68.06 J1.40 ; J1.40 58.15,66.05 ; J1.40 56.15,66.05 ; J1.40 58.15,68.06 ; J1.4 58.15,20.33 ; J1.4 58.15,22.34 ; J1.4 56.15,20.33 ; J1.4 56.15,22.34 ; 32.59,4.01 J5.1 ; J5.1 41.83,13.26 ; J5.1 41.83,4.01 ; J5.1 32.59,13.26 ; 2.9,59.11 J6.3 ; J6.3 2.9,61.74 ; J6.3 5.53,59.11 ; J1.16 58.15,37.58 ; J1.16 58.15,35.57 ; J1.16 56.15,35.57 ; J1.16 56.15,37.58 ; 28.44,30.8 JP8.3 ; JP8.3 30.44,30.8 ; JP8.3 30.44,32.8 ; JP8.3 28.44,32.8 ; J1.38 58.15,65.52 ; J1.38 56.15,65.52 ; J1.38 56.15,63.51 ; J1.38 58.15,63.51 ; J1.24 58.15,45.73 ; J1.24 58.15,47.74 ; J1.24 56.15,45.73 ; J1.24 56.15,47.74 ; J1.28 58.15,50.81 ; J1.28 56.15,52.82 ; J1.28 56.15,50.81 ; J1.28 58.15,52.82 ; 56.15,40.12 J1.18 ; J1.18 58.15,40.12 ; J1.18 58.15,38.11 ; J1.18 56.15,38.11 ; 56.15,55.89 J1.32 ; J1.32 58.15,55.89 ; J1.32 56.15,57.9 ; J1.32 58.15,57.9 ; 46.28,52.96 J2.4 ; J2.4 48.92,52.96 ; J2.4 48.92,55.6 ; J1.2 58.15,17.79 ; J1.2 56.15,19.8 ; J1.2 58.15,19.8 ; J1.2 56.15,17.79 ; J3.3 21.89,78.08 ; J3.3 21.89,75.44 ; J3.3 19.26,78.08 ; 19.26,70.36 J3.4 ; J3.4 21.89,73 ; J3.4 21.89,70.36 ; 18.1,58.43 JP4.3 ; JP4.3 20.1,56.43 ; JP4.3 20.1,58.43 ; JP4.3 18.1,56.43
  BOTTOM w0.559: 56.15,55.89 J1.32 ; J1.32 58.15,55.89 ; J1.32 58.15,57.9 ; J1.32 56.15,57.9 ; J1.6 58.15,24.88 ; J1.6 58.15,22.87 ; J1.6 56.15,22.87 ; J1.6 56.15,24.88 ; J1.38 58.15,65.52 ; J1.38 56.15,65.52 ; J1.38 58.15,63.51 ; J1.38 56.15,63.51 ; 55.8,41.66 J1.20 55.85,42.21 ; J1.36 58.15,62.98 ; J1.36 58.15,60.97 ; J1.36 56.15,62.98 ; J1.36 56.15,60.97 ; 48.8,13.11 TP3.1 ; TP3.1 51.48,13.11 ; TP3.1 48.8,15.8 ; TP3.1 51.48,15.8 ; 55.85,47.29 J1.24 55.8,46.74 ; J1.2 58.15,19.8 ; J1.2 56.15,17.79 ; J1.2 56.15,19.8 ; J1.2 58.15,17.79 ; J2.4 48.92,55.6 ; J2.4 46.28,52.96 ; J2.4 48.92,52.96 ; J6.3 5.53,59.11 ; J6.3 2.9,61.74 ; J6.3 2.9,59.11 ; JP10.3 49.52,27.67 ; JP10.3 49.52,29.68 ; JP10.3 47.51,27.67 ; 55.85,32.05 57.15,31.5 55.8,31.5 ; 56.15,52.82 J1.28 ; J1.28 58.15,50.81 ; J1.28 56.15,50.81 ; J1.28 58.15,52.82 ; 56.15,27.42 J1.8 ; J1.8 58.15,25.41 ; J1.8 58.15,27.42 ; J1.8 56.15,25.41 ; 7.98,59.11 J6.2 ; J6.2 10.61,59.11 ; J6.2 10.61,61.74 ; J6.5 10.61,64.19 ; J6.5 7.98,66.82 ; J6.5 10.61,66.82 ; TP1.1 8.53,74.06 ; TP1.1 5.84,71.38 ; TP1.1 5.84,74.06 ; TP1.1 8.53,71.38 ; 19.26,70.36 J3.4 ; J3.4 21.89,73 ; J3.4 21.89,70.36 ; J1.40 58.15,66.05 ; J1.40 58.15,68.06 ; J1.40 56.15,66.05 ; J1.40 56.15,68.06 ; 14.18,75.44 J3.2 ; J3.2 16.81,78.08 ; J3.2 14.18,78.08 ; J2.3 48.92,60.68 ; J2.3 48.92,58.04 ; J2.3 46.28,60.68 ; 2.9,66.82 J6.4 ; J6.4 2.9,64.19 ; J6.4 5.53,66.82 ; 56.15,53.35 J1.30 ; J1.30 58.15,55.36 ; J1.30 56.15,55.36 ; J1.30 58.15,53.35 ; J3.3 21.89,75.44 ; J3.3 21.89,78.08 ; J3.3 19.26,78.08 ; 41.2,60.68 J2.2 ; J2.2 41.2,58.04 ; J2.2 43.84,60.68 ; 14.18,73 J3.5 ; J3.5 14.18,70.36 ; J3.5 16.81,70.36 ; 56.15,22.34 J1.4 ; J1.4 58.15,22.34 ; J1.4 58.15,20.33 ; J1.4 56.15,20.33 ; 58.15,27.95 J1.10 56.15,27.95 ; 55.85,39.67 J1.18 55.8,39.12 ; 55.85,44.75 J1.22 55.8,44.2 ; 41.2,52.96 J2.5 ; J2.5 43.84,52.96 ; J2.5 41.2,55.6 ; J1.34 58.15,60.44 ; J1.34 58.15,58.43 ; J1.34 56.15,58.43 ; J1.34 56.15,60.44 ; 18.1,56.43 JP4.3 19.1,56.08 ; 55.8,34.04 J1.14 55.85,34.59 ; J5.1 41.83,4.01 ; J5.1 41.83,13.26 ; J5.1 32.59,4.01 ; J5.1 32.59,13.26 ; 58.15,50.28 J1.26 56.15,50.28
  vias: v1(1.4,47.32) v1(1.4,44.78) v1(1.7,34.62) v1(1.7,32.08) v1(1.78,78.23) v1(1.78,75.69) v1(1.78,9.65) v1(1.78,7.11) v1(1.96,72.72) v1(1.96,70.18) v1(2.67,46.05) v1(2.97,33.35) v1(3.05,76.96) v1(3.05,8.38) v1(3.23,71.45) v1(3.94,47.32) v1(3.94,44.78) v1(4.22,40.41) v1(4.22,37.87) v1(4.32,75.69) v1(4.24,34.62) v1(4.24,32.08) v1(4.32,9.65) v1(4.32,7.11) v1(4.5,72.72) v1(4.5,70.18) v1(5.49,39.14) v1(5.89,46.43) v1(6.76,40.41) v1(6.76,37.87) v1(6.86,87.12) v1(6.86,84.58) v1(7.24,81.53) v1(8.13,85.85) v1(9.4,87.12) v1(9.4,84.58) v1(9.78,81.53) v1(10.01,71.86) v1(10.01,69.32) v1(11.28,70.59) v1(12.19,77.72) v1(12.19,59.28) v1(12.19,56.74) v1(12.4,66.8) v1(12.4,64.26) v1(12.57,87.12) v1(12.57,84.58) v1(12.55,71.86) v1(12.55,69.32) v1(13.46,58.01) v1(13.67,65.53) v1(13.84,85.85) v1(14.73,59.28) v1(14.73,56.74) v1(14.94,66.8) v1(14.94,64.26) v1(15.11,87.12) v1(15.11,84.58) v1(16.48,44.91) v1(16.69,50.8) v1(17.17,49.99) v1(17.27,37.19) v1(17.27,34.65) v1(17.65,50.77) v1(18.16,81.66) v1(18.16,79.12) v1(18.19,49.96) v1(18.62,50.77) v1(18.54,35.92) v1(19.43,80.39) v1(19.56,87.12) v1(19.56,84.58) v1(19.81,37.19) v1(19.81,34.65) v1(20.7,81.66) v1(20.7,79.12) v1(20.83,85.85) v1(21.95,59.21) v1(22.02,48.95) v1(22.1,87.12) v1(22.1,84.58) v1(22.38,46.25) v1(23.22,48.95) v1(23.72,46.3) v1(24.59,48.97) v1(25.22,46.23) v1(25.27,80.77) v1(25.27,78.23) v1(25.27,4.57) v1(25.27,2.03) v1(25.91,87.12) v1(25.91,84.58) v1(25.86,48.49) v1(26.29,11.05) v1(26.29,8.51) v1(26.54,79.5) v1(26.54,3.3) v1(26.85,39.14) v1(27.18,85.85) v1(27.41,63.3) v1(27.48,61.19) v1(27.56,9.78) v1(27.81,80.77) v1(27.81,78.23) v1(27.81,4.57) v1(27.81,2.03) v1(28.19,60.12) v1(28.45,87.12) v1(28.83,11.05) v1(28.83,8.51) v1(29.54,61.09) v1(30.12,64.01) v1(30.66,40.92) v1(30.81,60.05) v1(30.73,45.21) v1(30.81,43.87) v1(30.76,42.42) v1(31.78,61.34) v1(33.1,77.62) v1(33.1,75.08) v1(33.1,69.98) v1(33.45,67.84) v1(33.71,36.83) v1(34.06,56.46) v1(34.37,76.35) v1(35.23,38.2) v1(35.46,85.47) v1(35.46,82.93) v1(35.56,36.8) v1(35.64,77.62) v1(36.07,56.46) v1(36.73,84.2) v1(36.78,30.3) v1(37.24,28.7) v1(37.92,65.1) v1(37.92,62.56) v1(38,85.47) v1(38,82.93) v1(38.81,29.74) v1(39.19,63.83) v1(40.08,31.01) v1(40.41,28.85) v1(40.46,65.1) v1(40.46,62.56) v1(42.14,45.36) v1(42.14,42.82) v1(42.21,40.26) v1(42.21,37.72) v1(42.19,26.21) v1(42.24,24.03) v1(43.05,4.57) v1(43.05,2.03) v1(43.41,44.09) v1(43.48,38.99) v1(44.02,65.28) v1(44.02,62.74) v1(44.32,3.3) v1(44.68,45.36) v1(44.68,42.82) v1(44.75,40.26) v1(44.75,37.72) v1(45.29,64.01) v1(45.59,4.57) v1(45.59,2.03) v1(46.08,72.34) v1(46.1,10.92) v1(46.1,8.38) v1(46.56,65.28) v1(46.56,62.74) v1(47.37,9.65) v1(48.16,72.29) v1(48.64,10.92) v1(48.64,8.38) v1(49.4,78.23) v1(49.4,75.69) v1(49.45,65.58) v1(49.45,63.04) v1(50.67,76.96) v1(50.72,64.31) v1(51.56,19.94) v1(51.56,17.4) v1(51.56,10.92) v1(51.56,8.38) v1(51.94,87.12) v1(51.94,84.58) v1(51.94,78.23) v1(51.94,75.69) v1(51.99,65.58) v1(51.99,63.04) v1(51.94,58.55) v1(51.94,56.01) v1(52.2,25.65) v1(52.2,23.11) v1(52.58,4.57) v1(52.58,2.03) v1(52.83,18.67) v1(52.83,9.65) v1(53.21,85.85) v1(53.21,57.28) v1(53.47,24.38) v1(53.87,33.73) v1(53.85,3.3) v1(53.98,72.52) v1(54.1,19.94) v1(54.1,17.4) v1(54.1,10.92) v1(54.1,8.38) v1(54.48,87.12) v1(54.48,84.58) v1(54.48,58.55) v1(54.48,56.01) v1(54.56,35.81) v1(54.74,25.65) v1(54.74,23.11) v1(55.04,32.54) v1(55.12,4.57) v1(55.12,2.03) v1(55.24,73.79) v1(55.24,71.25) v1(55.32,34.85) v1(56.52,15.62) v1(56.52,13.08) v1(57.78,14.35) v1(58.29,72.52) v1(58.29,69.98) v1(58.93,87.12) v1(58.93,84.58) v1(58.93,10.92) v1(58.93,8.38) v1(58.93,4.57) v1(58.93,2.03) v1(59.05,15.62) v1(59.05,13.08) v1(59.56,71.25) v1(60.2,85.85) v1(60.2,9.65) v1(60.2,3.3) v1(60.83,72.52) v1(60.83,69.98) v1(61.47,87.12) v1(61.47,84.58) v1(61.47,10.92) v1(61.47,8.38) v1(61.47,4.57) v1(61.47,2.03) v3(27.05,24.26) v3(27.05,23.56) v3(27.05,22.86) v3(27.05,22.16) v3(27.05,21.46) v3(27.75,24.26) v3(27.75,23.56) v3(27.75,22.86) v3(27.75,22.16) v3(27.75,21.46) v3(28.45,24.26) v3(28.45,23.56) v3(28.45,22.86) v3(28.45,22.16) v3(28.45,21.46) v3(29.15,24.26) v3(29.15,23.56) v3(29.15,22.86) v3(29.15,22.16) v3(29.15,21.46) v3(29.85,24.26) v3(29.85,23.56) v3(29.85,22.86) v3(29.85,22.16) v3(29.85,21.46)
ADC_CLK: length 21.1
  TOP w0.184: U3.1 24.05,63.88 JP3.1 27.69,64.85 31.04,68.2 31.04,71.83 29.72,73.15 29.51,73.15
CLK_3.3V: length 49.9
  TOP w0.178: JP1.1 43.74,73.43 C8.1 50.29,73.43 JP7.1
  TOP w0.381: JP4.1 C6.1 ; U3.6 v1(27.83,55.91)
  TOP w0.508: R8.1 v1(23.44,70.84)
  TOP w0.559: 37.52,23.42 TP4.1 ; TP4.1 40.21,23.42 ; TP4.1 37.52,26.11 ; TP4.1 40.21,26.11
  BOTTOM w0.559: 49.05,72.19 JP7.1 ; JP7.1 51.64,74.78 ; JP7.1 51.64,72.19 ; JP7.1 49.05,74.78 ; TP4.1 40.21,26.11 ; TP4.1 37.52,26.11 ; TP4.1 40.21,23.42 ; TP4.1 37.52,23.42 ; 17.75,61.16 JP4.1 ; JP4.1 20.45,63.86 ; JP4.1 20.45,61.16 ; JP4.1 17.75,63.86 ; JP1.1 45.06,72.11 ; JP1.1 45.06,74.8 ; JP1.1 42.37,72.11 ; JP1.1 42.37,74.8
  vias: v1(29.72,18.92) v1(30.35,19.94) v1(30.61,17.91) v1(30.99,20.96) v1(31.24,18.92) v1(31.88,17.91) v1(32,21.08) v1(32.13,19.56) v1(32.26,22.73) v1(33.91,23.75) v1(33.91,22.61) v1(34.92,24.89) v1(34.92,22.23) v1(35.81,24.64) v1(36.2,23.24) v1(36.45,26.16) v1(37.46,22.35) v1(39.5,22.48)
CLK_OUT: length 13.3
  TOP w0.184: J2.1 38.89,56.82 37.29,55.22 R16.2
CLKOUT: length 1.8
  TOP w0.184: R16.1 31.4,55.26 U3.5
D0: length 6.9
  TOP w0.178: v1(37.21,39.12) 36.32,39.12 34.03,41.41 U1.3
  BOTTOM w0.178: U5.3 v1(37.21,39.12)
D1: length 6.7
  TOP w0.178: v1(37.21,40.39) 36.32,40.39 34.65,42.06 U1.4
  BOTTOM w0.178: 38.74,40.39 v1(37.21,40.39)
D2: length 6.4
  TOP w0.178: v1(37.21,41.66) 36.2,41.66 35.14,42.71 U1.5
  BOTTOM w0.178: U5.5 v1(37.21,41.66)
D3: length 6.2
  TOP w0.178: v1(37.21,42.93) 36.07,42.93 35.63,43.36 U1.6
  BOTTOM w0.178: 38.74,42.93 v1(37.21,42.93)
D4: length 6.1
  TOP w0.178: v1(37.21,44.2) 36.58,44.2 36.32,43.94 32.84,43.94 U1.7
  BOTTOM w0.178: U5.7 v1(37.21,44.2)
D5: length 6.3
  TOP w0.178: v1(37.21,45.47) 36.07,45.47 35.27,44.66 U1.8
  BOTTOM w0.178: U5.8 v1(37.21,45.47)
D6: length 6.6
  TOP w0.178: U1.9 34.39,45.31 35.81,46.74 v1(37.21,46.74)
  BOTTOM w0.178: U5.9 v1(37.21,46.74)
D7: length 6.8
  TOP w0.178: v1(37.21,48.01) 36.07,48.01 34.03,45.96 U1.10
  BOTTOM w0.178: U5.10 v1(37.21,48.01)
OE: length 6.4
  TOP w0.178: U3.2 22.51,56.56 JP4.2
OSC: length 7.9
  TOP w0.184: J3.1 18.11,74.14 R9.2 C9.1
OSC1: length 6.8
  TOP w0.184: C9.2 R10.1 ; R10.1 25.91,71.86 R8.2 ; R10.1 28.24,71.88 JP2.3
X1Y3: length 69.1
  TOP w0.178: R18.2 36.22,57.2 41,61.98 49.35,61.98 50.72,60.6 50.72,22.94 52.2,21.46 54.61,21.46 56.13,19.94 58.55,19.94 J1.1
N19769118: length 1.7
  TOP w0.178: Y1.3 47.67,67.71 R19.2
N19769226: length 22
  TOP w0.178: R19.1 38.68,66.52 JP2.1
N19799665: length 4.6
  TOP w0.178: U3.3 25.23,55.91 26.37,57.05 R15.2
N19799687: length 1.8
  TOP w0.184: U3.8 31.14,57.21 31.15,57.2 R18.1
N19818955: length 12.6
  BOTTOM w0.178: U5.14 55.12,49.28 56.39,48.01 58.42,48.01 J1.23
N19818957: length 13.1
  BOTTOM w0.178: U5.15 53.72,48.01 56.26,45.47 58.42,45.47 J1.21
N19818959: length 13.7
  BOTTOM w0.178: J1.19 58.42,42.93 56.13,42.93 52.32,46.74 U5.16
N19818961: length 14.2
  BOTTOM w0.178: J1.17 58.42,40.39 56.26,40.39 51.18,45.47 U5.17
N19819026: length 18.8
  BOTTOM w0.178: 48.12,40.39 50.29,40.39 52.91,37.77 52.91,33.45 56.13,30.23 58.42,30.23 J1.9
N19819028: length 17.6
  BOTTOM w0.178: 59.69,31.5 58.42,32.77 56.13,32.77 53.72,35.18 53.72,38.23 50.29,41.66 U5.20
N19819030: length 16.1
  BOTTOM w0.178: J1.13 58.42,35.31 56.39,35.31 54.69,37.01 54.69,38.4 50.16,42.93 48.12,42.93
N19819032: length 15.2
  BOTTOM w0.178: U5.18 50.8,44.2 55.22,39.78 55.22,38.89 56.26,37.85 58.42,37.85 J1.15
N19819185: length 9.4
  TOP w0.178: JP3.2 31.11,62.31 JP5.1
N19819194: length 22.1
  TOP w0.178: U1.12 34.23,47.26 v1(36.14,49.17)
  BOTTOM w0.178: JP5.2 36.25,62.31 38.89,59.66 38.89,54.84 36.14,52.1 v1(36.14,49.17)
N19819218: length 6.6
  TOP w0.178: R15.1 32.79,58.9 JP5.3
N19821064: length 2.7
  TOP w0.178: JP1.2 43.73,70.93 Y1.1
N19821339: length 2.7
  TOP w0.178: JP7.2 50.33,70.93 Y1.4
N19861116: length 27.5
  TOP w0.178: 29.27,44.01 29.27,37.03 29.27,37.03 JP8.1 ; 29.27,44.01 U1.18 ; 29.27,44.01 29.27,45.54 28.84,45.96 U1.15 U1.14 25.9,46.61 25.4,47.12 25.4,47.62 25.15,47.88 C16.1 C2.1 C3.1 19.76,47.88 C1.1 19.68,47.96 19.68,49.02 20.45,49.78 FB1.2 FB4.2
N19861142: length 14
  TOP w0.178: FB1.1 C17.1 C5.1 C4.1 26.54,50.22 26.54,49.15 27.12,48.57 U1.13 27.14,47.24 29.59,47.24 30.22,46.61 U1.11
N19864072: length 10.2
  TOP w0.178: J6.1 6.76,59.56 5.05,57.86 R22.1 5.82,57.05 6.73,56.13 C21.1
N19864307: length 4.1
  TOP w0.178: 23.11,43.31 24.64,43.31 C22.1 24.84,43.36
  TOP w0.184: 24.84,43.36 U1.19
N19864545: length 7.8
  TOP w0.178: U1.1 31.65,40.11 31.34,39.8 31.34,36.25 JP8.2
N19865533: length 16.2
  TOP w0.178: U1.16 22.12,45.31 21.26,46.18 15.8,46.18 JP9.3
N19865546: length 15.5
  TOP w0.178: JP9.2 14.48,46.86 15.54,45.8 19.35,45.8 20.51,44.64 C7.1 20.61,44.66 U1.17
N19865555: length 4.1
  TOP w0.178: JP9.1 TP5.1
N19865562: length 16.6
  TOP w0.178: JP6.2 16.51,42.04 21.84,42.04 23.13,40.75 C15.1 23.19,40.76 U1.23
N19865571: length 15.5
  TOP w0.178: JP6.3 14.48,40.77 16.13,42.42 23.62,42.42 24.63,41.41 U1.22
N19865580: length 4.2
  TOP w0.178: JP6.1 TP6.1
N19873407: length 2.6
  TOP w0.203: C20.1 24.27,22.21 U2.14
N19873435: length 2
  TOP w0.203: U2.8 R14.2
N19873437: length 2.2
  TOP w0.178: R12.2 25.01,24.16
  TOP w0.203: 25.01,24.16 U2.11
N19873439: length 2.8
  TOP w0.203: U2.12 23.4,23.51 R11.2
N19873449: length 2.3
  TOP w0.203: R13.2 27.15,27.59 U2.10
N19874302: length 5
  TOP w0.178: U4.4 8.68,30.31 9.88,29.11 Q1.4
N19886844: length 13.8
  BOTTOM w0.178: U5.22 50.57,39.12 51.97,37.72 51.97,32.21 50.98,31.22 JP10.2
N19913177: length 22.1
  TOP w0.178: R21.2 15.88,43.31 13.59,45.59 10.92,45.59 9.27,47.24 8.89,47.24 6.73,49.4 R30.1 R26.1 C21.2

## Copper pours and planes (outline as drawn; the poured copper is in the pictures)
5V on TOP (solid shape): 8.06,22.3 4.25,22.3 4.25,26.82 8.06,26.82
5V on TOP: 5.59,1.78 5.59,10.67 1.78,14.48 1.78,30.99 6.48,30.99 6.48,29.59 5.71,29.59 5.08,28.96 5.08,26.8 8.13,26.8 8.13,22.23 7.11,22.23 6.1,21.21 6.1,19.56 6.6,19.05 13.97,19.05 16.13,16.89 19.81,16.89 23.5,13.21 23.5,1.78
5V on BOTTOM: 5.59,1.78 5.59,19.05 5.18,19.46 5.18,27.03 5.23,27.08 8.43,27.08 8.43,19.05 10.79,19.05 10.86,18.99 14.03,18.99 15.75,17.27 19.3,17.27 23.5,13.08 23.5,1.78
+3.3V on TOP: 40.39,17.4 40.39,21.08 42.04,22.73 48.26,22.73 48.26,17.4
+3.3V on TOP: 21.36,54 37.52,54 40.18,51.33 44.4,51.33 45.14,50.6 45.14,47.55 45.11,47.52 40.61,47.52 35.74,52.4 21.36,52.4
+3.3V on BOTTOM: 40.26,17.4 40.26,20.96 42.04,22.73 43.18,22.73 43.18,32.05 40.56,32.05 40.54,32.08 40.54,51.28 46.2,51.28 46.2,38.1 49.35,38.1 49.35,38.05 50.62,36.78 50.62,32.72 47.09,32.72 46.74,32.36 46.74,26.7 48.39,25.04 48.39,17.4
+5V on TOP: 11.68,24.64 11.68,17.27 27.18,17.27 27.18,20.57 26.04,21.72 26.04,24.64 21.49,24.64 21.49,25.32 24.43,28.27 31.93,28.27 35,31.34 37.26,31.34 37.26,35.1 35.38,35.1 30.91,30.63 26.57,30.63 24.56,32.64 21.46,32.64 21.46,30.91 21.18,30.63 21.13,30.63 18.87,28.37 16.13,28.37 16.13,24.64 ; 1 cut-out
+5V on TOP: 9.07,55.4 17.81,55.4 19.53,53.67 19.53,52.45 19.3,52.22 10.44,52.22 10.41,52.2 10.41,50.55 9.07,50.55
+5V on BOTTOM: 11.68,24.64 11.68,20.57 13.21,20.57 16,17.78 19.94,17.78 20.45,17.27 27.18,17.27 27.18,20.57 26.04,21.72 26.04,24.59 26.06,24.61 26.06,38.3 20.14,44.22 20.14,54.05 18.64,55.55 10.11,55.55 9.3,54.74 9.3,53.11 9.02,52.83 9.02,50.55 10.54,50.55 10.57,50.57 10.57,51.84 10.9,51.51 15.16,51.51 15.16,24.69 15.11,24.64
GND on TOP: 0.51,0.51 0.51,88.39 62.99,88.39 62.99,0.51 ; 5 cut-outs
GND on TOP: 26.21,42.93 26.21,41.88 28.02,41.88 28.02,42.93
GND on BOTTOM: 0.51,0.51 0.51,88.39 62.99,88.39 62.99,0.51 ; 4 cut-outs
GND on GND1, GND2: 1.27,1.27 1.27,87.63 62.23,87.63 62.23,1.27
CLK_3.3V on TOP: 29.34,17.4 29.34,20.57 30.73,20.57 30.73,23.11 32.39,23.11 36.07,26.8 41.02,26.8 41.02,23.11 38.61,20.7 38.61,18.92 38.48,18.8 32.51,18.8 32.51,17.4
CLK_3.3V on BOTTOM: 29.34,17.4 29.34,20.57 30.56,21.79 30.56,26.29 28.04,28.8 28.04,55.7 27.99,55.75 20.7,55.75 16.28,60.17 16.28,68.83 22.02,68.83 23.14,69.95 23.14,71.83 32.28,71.83 37.06,76.61 52.32,76.61 52.32,67.44 35.86,67.44 34.04,65.61 34.04,62.64 34.77,61.9 34.77,39.95 31.85,37.03 31.85,29.39 33.5,27.74 40.74,27.74 40.77,27.71 40.77,22.99 39.37,21.59 39.37,21.46 36.83,21.46 32.77,17.4 ; 1 cut-out
N19874252 on TOP: 9.14,25.53 9.14,21.46 8.89,21.21 7.87,21.21 7.87,19.68 10.79,19.68 11.05,19.94 11.05,21.21 10.54,21.72 10.54,25.53
N19887644 on BOTTOM: 37.87,38.15 37.87,32.66 39.65,32.66 39.65,38.15

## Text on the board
BOTTOM: BOTTOM SIDE
Board Geometry/Soldermask Bottom: SOLDERMASK BOTTOM
Ref Des/Silkscreen Bottom: SILKSCREEN BOTTOM | DC021A
User.Comments: ADC1175EVM REV A | SEE NOTE 5 | ASSEMBLY DRAWING,
TOP: TOP SIDE
Ref Des/Assembly Top: GND
Board Geometry/Soldermask Top: SOLDERMASK TOP
Ref Des/Silkscreen Top: CLK_3.3V | VRT | VRTS | VRB | VRBS | ADC_CLK | OSC1 | +3.3V | D4 | D3 | D2 | D1 | D6 | D5 | D0 | D7 | GND | OE | INH | VDD | +5V | BYPASS | BYPASS2 | 29 | SILKSCREEN TOP | LABEL
GND1: GROUND PLANE 1
GND2: GROUND PLANE 2
PAGE_OUTLINE: PASTEMASK TOP
PASTEMASK_BOTTOM: PASTEMASK BOTTOM
User.8: 3. IPC-A-610 / ACCEPTABILITY OF ELECTRONIC ASSEMBLIES, CLASS2, CURRENT REVISION. | 4. REMOVE THE METAL TAB ON THE BANANA JACKS BEFORE  MOUNTING THEM ON | THE BOARD. USE LOCTITE THREADLOCKER BLUE 242 (OR EQUIVALENT) WHEN | INSTALLING THE BANANA JACKS. | 2. MARK BOARD'S SILKSCREEN WITH THE SERIAL NUMBER. | 1. REFER TO IPC FILE FOR SPECIFIC COMPONENT LOCATION INFORMATION. | 5. MARK BOARD'S SILKSCREEN WITH STICKER/LABELFOR THE DEVICE THAT IS USED. | THIS DRAWING IS INTENDED TO HELP IN THE ASSEMBLY OF THE DESIGN.
User.11: FIGURE | SIZE | 10.0 | 12.0 | 38.0 | 40.0 | 42.0 | 62.0 | 67.0 | 125.0 | 315.0 | DRILL CHART: TOP to BOTTOM | ALL UNITS ARE IN MILS | PLATED | QTY | 381 | 40 | 4 | 27 | 7 | 3 | 12 | 2
